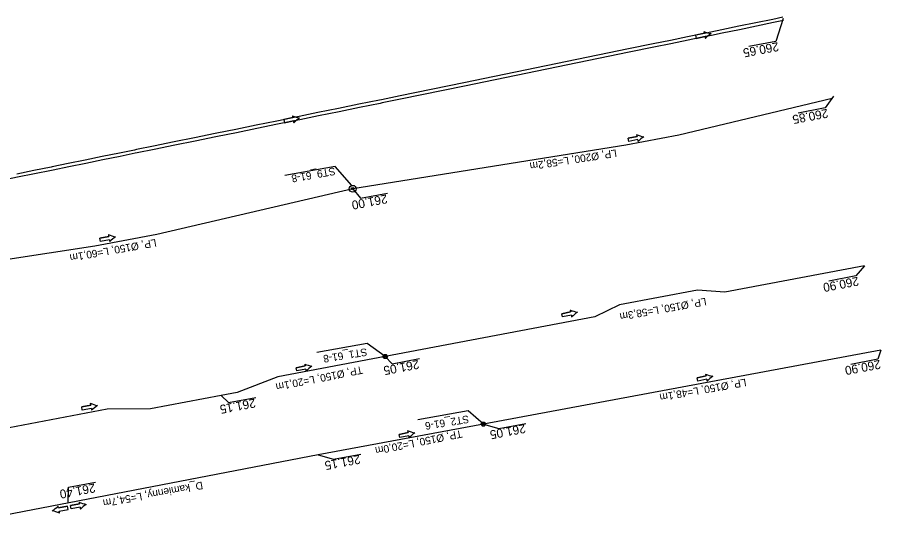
# Model space of a CAD drawing. Extents: x -1 to 65640748, y -22 to 5530284.
# Drawn here: x 6557517.6 to 6557620.4, y 5528681 to 5528743.4 of the extents above; entities that cross this region are included whole.
import ezdxf

# ---------------------------------------------------------------- set-up
doc = ezdxf.new("R2010")
doc.units = 0
for name, color, linetype in [('TOR_PROF-studnie i osadniki', 7, 'Continuous'), ('TOR_PS_ODW-drenaze', 7, 'Continuous'), ('TOR_PS_ODW-drenokolektory', 7, 'Continuous'), ('TOR_PS_ODW-studnie PEHD', 7, 'Continuous'), ('TOR_PS_OPIS_O-opisy rurociagow', 7, 'Continuous'), ('TOR_PS_OPIS_O-opisy studni', 7, 'Continuous'), ('TOR_PS_OPIS_T-INFO', 7, 'Continuous'), ('TOR_PS_T-rowy otwarte umocnione', 7, 'Continuous')]:
    doc.layers.add(name, color=color, linetype=linetype)

msp = doc.modelspace()

# ---------------------------------------------------------------- linework, layer by layer
at = {"layer": 'TOR_PROF-studnie i osadniki'}
for centre, radius in [((6557561.36, 5528703.01), 0.25), ((6557561.36, 5528703.01), 0.125), ((6557573.05, 5528694.97), 0.25), ((6557573.05, 5528694.97), 0.125)]:
    msp.add_circle(centre, radius, dxfattribs=at)
at = {"layer": 'TOR_PS_ODW-drenaze'}
for points in [[(6557620.36, 5528703.76), (6557573.05, 5528694.97)], [(6557561.36, 5528703.01), (6557548.59, 5528700.58), (6557543.74, 5528698.75), (6557541.85, 5528698.39)], [(6557541.85, 5528698.39), (6557533.42, 5528696.79), (6557528.24, 5528696.73), (6557502.37, 5528691.82)], [(6557573.05, 5528694.97), (6557553.38, 5528691.31)], [(6557553.38, 5528691.32), (6557499.62, 5528680.97)]]:
    msp.add_lwpolyline(points, dxfattribs=at)
at = {"layer": 'TOR_PS_ODW-drenokolektory'}
for points in [[(6557614.59, 5528733.72), (6557596.33, 5528729.36), (6557589.99, 5528728.16), (6557557.49, 5528722.98)], [(6557557.49, 5528722.98), (6557534.16, 5528717.55), (6557526.81, 5528716.13), (6557498.52, 5528711.81), (6557498.52, 5528711.81)], [(6557618.42, 5528713.82), (6557601.81, 5528710.67), (6557598.53, 5528710.92), (6557589.27, 5528709.16), (6557586.31, 5528707.74), (6557561.36, 5528703.01)]]:
    msp.add_lwpolyline(points, dxfattribs=at)
msp.add_circle((6557557.49, 5528722.98), 0.145, dxfattribs=at)
at = {"layer": 'TOR_PS_ODW-studnie PEHD'}
for centre, radius in [((6557557.49, 5528722.98), 0.4), ((6557561.36, 5528703.01), 0.25), ((6557561.36, 5528703.01), 0.112), ((6557573.05, 5528694.97), 0.25), ((6557573.05, 5528694.97), 0.112)]:
    msp.add_circle(centre, radius, dxfattribs=at)
at = {"layer": 'TOR_PS_OPIS_O-opisy rurociagow'}
for p, q in [((6557599.36, 5528741.48), (6557598.29, 5528741.26)), ((6557599.36, 5528741.48), (6557598.29, 5528741.26)), ((6557598.29, 5528741.26), (6557598.37, 5528740.87)), ((6557598.29, 5528741.26), (6557598.37, 5528740.87)), ((6557598.37, 5528740.87), (6557599.44, 5528741.09)), ((6557599.44, 5528741.09), (6557598.37, 5528740.87)), ((6557550.38, 5528731.44), (6557549.31, 5528731.23)), ((6557550.38, 5528731.44), (6557549.31, 5528731.23)), ((6557549.31, 5528731.23), (6557549.39, 5528730.83)), ((6557549.31, 5528731.23), (6557549.39, 5528730.83)), ((6557549.39, 5528730.83), (6557550.46, 5528731.05)), ((6557550.46, 5528731.05), (6557549.39, 5528730.83)), ((6557590.27, 5528728.99), (6557591.34, 5528729.21)), ((6557591.34, 5528729.21), (6557590.27, 5528728.99)), ((6557590.35, 5528728.6), (6557590.27, 5528728.99)), ((6557590.35, 5528728.6), (6557590.27, 5528728.99)), ((6557591.42, 5528728.82), (6557590.35, 5528728.6)), ((6557591.42, 5528728.82), (6557590.35, 5528728.6)), ((6557527.39, 5528717.08), (6557528.46, 5528717.3)), ((6557528.46, 5528717.3), (6557527.39, 5528717.08)), ((6557527.47, 5528716.69), (6557527.39, 5528717.08)), ((6557527.47, 5528716.69), (6557527.39, 5528717.08)), ((6557528.54, 5528716.91), (6557527.47, 5528716.69)), ((6557528.54, 5528716.91), (6557527.47, 5528716.69)), ((6557582.37, 5528708.11), (6557583.44, 5528708.33)), ((6557583.44, 5528708.33), (6557582.37, 5528708.11)), ((6557582.46, 5528707.72), (6557582.37, 5528708.11)), ((6557582.46, 5528707.72), (6557582.37, 5528708.11)), ((6557583.53, 5528707.94), (6557582.46, 5528707.72)), ((6557583.53, 5528707.94), (6557582.46, 5528707.72)), ((6557550.77, 5528701.68), (6557551.84, 5528701.9)), ((6557551.84, 5528701.9), (6557550.77, 5528701.68)), ((6557550.85, 5528701.29), (6557550.77, 5528701.68)), ((6557550.85, 5528701.29), (6557550.77, 5528701.68)), ((6557551.92, 5528701.51), (6557550.85, 5528701.29)), ((6557551.92, 5528701.51), (6557550.85, 5528701.29)), ((6557598.5, 5528700.48), (6557599.57, 5528700.7)), ((6557599.57, 5528700.7), (6557598.5, 5528700.48)), ((6557598.58, 5528700.09), (6557598.5, 5528700.48)), ((6557598.58, 5528700.09), (6557598.5, 5528700.48)), ((6557599.65, 5528700.31), (6557598.58, 5528700.09)), ((6557599.65, 5528700.31), (6557598.58, 5528700.09)), ((6557525.23, 5528697.04), (6557526.3, 5528697.23)), ((6557526.3, 5528697.23), (6557525.23, 5528697.04)), ((6557525.3, 5528696.64), (6557525.23, 5528697.04)), ((6557525.3, 5528696.64), (6557525.23, 5528697.04)), ((6557526.38, 5528696.84), (6557525.3, 5528696.64)), ((6557526.38, 5528696.84), (6557525.3, 5528696.64)), ((6557563.01, 5528693.75), (6557564.08, 5528693.97)), ((6557564.08, 5528693.97), (6557563.01, 5528693.75)), ((6557563.09, 5528693.36), (6557563.01, 5528693.75)), ((6557563.09, 5528693.36), (6557563.01, 5528693.75)), ((6557564.16, 5528693.58), (6557563.09, 5528693.36)), ((6557564.16, 5528693.58), (6557563.09, 5528693.36)), ((6557523.52, 5528685.21), (6557522.45, 5528685)), ((6557522.45, 5528685), (6557523.52, 5528685.21)), ((6557523.6, 5528684.82), (6557523.52, 5528685.21)), ((6557523.6, 5528684.82), (6557523.52, 5528685.21)), ((6557523.89, 5528685.28), (6557524.96, 5528685.47)), ((6557524.96, 5528685.47), (6557523.89, 5528685.28)), ((6557523.96, 5528684.89), (6557523.89, 5528685.28)), ((6557523.96, 5528684.89), (6557523.89, 5528685.28)), ((6557525.03, 5528685.08), (6557523.96, 5528684.89)), ((6557525.03, 5528685.08), (6557523.96, 5528684.89)), ((6557522.53, 5528684.61), (6557523.6, 5528684.82)), ((6557522.53, 5528684.61), (6557523.6, 5528684.82))]:
    msp.add_line(p, q, dxfattribs=at)
for points in [[(6557599.3, 5528741.7), (6557599.3, 5528741.7)], [(6557599.47, 5528740.87), (6557599.47, 5528740.87)], [(6557550.32, 5528731.66), (6557550.32, 5528731.66)], [(6557550.49, 5528730.83), (6557550.49, 5528730.83)], [(6557591.29, 5528729.43), (6557591.29, 5528729.43)], [(6557591.46, 5528728.59), (6557591.46, 5528728.59)], [(6557528.41, 5528717.52), (6557528.41, 5528717.52)], [(6557528.58, 5528716.69), (6557528.58, 5528716.69)], [(6557583.39, 5528708.55), (6557583.39, 5528708.55)], [(6557583.56, 5528707.71), (6557583.56, 5528707.71)], [(6557551.78, 5528702.12), (6557551.78, 5528702.12)], [(6557551.96, 5528701.29), (6557551.96, 5528701.29)], [(6557599.51, 5528700.92), (6557599.51, 5528700.92)], [(6557599.68, 5528700.08), (6557599.68, 5528700.08)], [(6557526.25, 5528697.45), (6557526.25, 5528697.45)], [(6557526.4, 5528696.61), (6557526.4, 5528696.61)], [(6557564.03, 5528694.19), (6557564.03, 5528694.19)], [(6557564.2, 5528693.36), (6557564.2, 5528693.36)], [(6557522.41, 5528685.22), (6557522.41, 5528685.22)], [(6557524.91, 5528685.69), (6557524.91, 5528685.69)], [(6557522.58, 5528684.39), (6557522.58, 5528684.39)], [(6557525.06, 5528684.86), (6557525.06, 5528684.86)]]:
    msp.add_lwpolyline(points, dxfattribs=at)
for centre, radius, start, end in [((6557601.15, 5528746.26), 4.92, 247.9079, 258.2898), ((6557599.76, 5528741.7), 0.458, 180.0225, 208.4837), ((6557601.15, 5528746.26), 4.92, 247.9079, 258.2898), ((6557599.76, 5528741.7), 0.458, 180.0225, 208.4837), ((6557602.97, 5528737.41), 4.92, 124.9458, 135.3277), ((6557602.97, 5528737.41), 4.92, 124.9458, 135.3277), ((6557599.9, 5528741.05), 0.458, 174.7519, 203.2131), ((6557599.9, 5528741.05), 0.458, 174.7519, 203.2131), ((6557552.18, 5528736.22), 4.92, 247.8203, 258.2021), ((6557550.78, 5528731.66), 0.458, 179.9349, 208.3961), ((6557552.18, 5528736.22), 4.92, 247.8203, 258.2021), ((6557550.78, 5528731.66), 0.458, 179.9349, 208.3961), ((6557553.98, 5528727.37), 4.92, 124.8582, 135.24), ((6557553.98, 5528727.37), 4.92, 124.8582, 135.24), ((6557550.91, 5528731.01), 0.458, 174.6642, 203.1255), ((6557550.91, 5528731.01), 0.458, 174.6642, 203.1255), ((6557591.75, 5528729.43), 0.458, 180.0627, 208.524), ((6557593.13, 5528733.98), 4.92, 247.9482, 258.33), ((6557593.13, 5528733.98), 4.92, 247.9482, 258.33), ((6557591.75, 5528729.43), 0.458, 180.0627, 208.524), ((6557594.96, 5528725.14), 4.92, 124.9861, 135.3679), ((6557594.96, 5528725.14), 4.92, 124.9861, 135.3679), ((6557591.88, 5528728.77), 0.458, 174.7921, 203.2533), ((6557591.88, 5528728.77), 0.458, 174.7921, 203.2533), ((6557528.87, 5528717.52), 0.458, 180.0627, 208.524), ((6557530.25, 5528722.08), 4.92, 247.9482, 258.33), ((6557530.25, 5528722.08), 4.92, 247.9482, 258.33), ((6557528.87, 5528717.52), 0.458, 180.0627, 208.524), ((6557529, 5528716.87), 0.458, 174.7921, 203.2533), ((6557529, 5528716.87), 0.458, 174.7921, 203.2533), ((6557532.08, 5528713.23), 4.92, 124.9861, 135.3679), ((6557532.08, 5528713.23), 4.92, 124.9861, 135.3679), ((6557583.85, 5528708.55), 0.458, 180.0627, 208.524), ((6557585.24, 5528713.1), 4.92, 247.9482, 258.33), ((6557585.24, 5528713.1), 4.92, 247.9482, 258.33), ((6557583.85, 5528708.55), 0.458, 180.0627, 208.524), ((6557583.98, 5528707.89), 0.458, 174.7921, 203.2533), ((6557583.98, 5528707.89), 0.458, 174.7921, 203.2533), ((6557587.06, 5528704.26), 4.92, 124.9861, 135.3679), ((6557587.06, 5528704.26), 4.92, 124.9861, 135.3679), ((6557552.24, 5528702.12), 0.458, 180.0627, 208.524), ((6557553.63, 5528706.68), 4.92, 247.9482, 258.33), ((6557553.63, 5528706.68), 4.92, 247.9482, 258.33), ((6557552.24, 5528702.12), 0.458, 180.0627, 208.524), ((6557552.38, 5528701.47), 0.458, 174.7921, 203.2533), ((6557552.38, 5528701.47), 0.458, 174.7921, 203.2533), ((6557555.46, 5528697.83), 4.92, 124.9861, 135.3679), ((6557555.46, 5528697.83), 4.92, 124.9861, 135.3679), ((6557599.97, 5528700.92), 0.458, 180.0627, 208.524), ((6557601.36, 5528705.47), 4.92, 247.9482, 258.33), ((6557601.36, 5528705.47), 4.92, 247.9482, 258.33), ((6557599.97, 5528700.92), 0.458, 180.0627, 208.524), ((6557600.11, 5528700.26), 0.458, 174.7921, 203.2533), ((6557600.11, 5528700.26), 0.458, 174.7921, 203.2533), ((6557603.18, 5528696.63), 4.92, 124.9861, 135.3679), ((6557603.18, 5528696.63), 4.92, 124.9861, 135.3679), ((6557526.71, 5528697.44), 0.458, 178.6495, 207.1107), ((6557528.21, 5528701.96), 4.92, 246.5349, 256.9167), ((6557528.21, 5528701.96), 4.92, 246.5349, 256.9167), ((6557526.71, 5528697.44), 0.458, 178.6495, 207.1107), ((6557526.83, 5528696.78), 0.458, 173.3788, 201.8401), ((6557526.83, 5528696.78), 0.458, 173.3788, 201.8401), ((6557529.82, 5528693.07), 4.92, 123.5728, 133.9546), ((6557529.82, 5528693.07), 4.92, 123.5728, 133.9546), ((6557564.49, 5528694.19), 0.458, 180.0627, 208.524), ((6557565.87, 5528698.75), 4.92, 247.9482, 258.33), ((6557565.87, 5528698.75), 4.92, 247.9482, 258.33), ((6557564.49, 5528694.19), 0.458, 180.0627, 208.524), ((6557564.62, 5528693.54), 0.458, 174.7921, 203.2533), ((6557564.62, 5528693.54), 0.458, 174.7921, 203.2533), ((6557567.7, 5528689.9), 4.92, 124.9861, 135.3679), ((6557567.7, 5528689.9), 4.92, 124.9861, 135.3679), ((6557518.94, 5528688.7), 4.92, 304.5497, 314.9316), ((6557518.94, 5528688.7), 4.92, 304.5497, 314.9316), ((6557521.99, 5528685.04), 0.458, 354.3558, 22.817), ((6557521.99, 5528685.04), 0.458, 354.3558, 22.817), ((6557525.37, 5528685.68), 0.458, 178.6495, 207.1107), ((6557526.87, 5528690.21), 4.92, 246.5349, 256.9167), ((6557526.87, 5528690.21), 4.92, 246.5349, 256.9167), ((6557525.37, 5528685.68), 0.458, 178.6495, 207.1107), ((6557525.49, 5528685.03), 0.458, 173.3788, 201.8401), ((6557525.49, 5528685.03), 0.458, 173.3788, 201.8401), ((6557528.48, 5528681.32), 4.92, 123.5728, 133.9546), ((6557528.48, 5528681.32), 4.92, 123.5728, 133.9546), ((6557520.7, 5528679.84), 4.92, 67.5119, 77.8937), ((6557520.7, 5528679.84), 4.92, 67.5119, 77.8937), ((6557522.12, 5528684.39), 0.458, 359.6264, 28.0877), ((6557522.12, 5528684.39), 0.458, 359.6264, 28.0877)]:
    msp.add_arc(centre, radius, start, end, dxfattribs=at)
at = {"layer": 'TOR_PS_OPIS_T-INFO'}
for points in [[(6557608.76, 5528743.22), (6557607.87, 5528740.52), (6557604.64, 5528739.89)], [(6557614.73, 5528734.01), (6557613.76, 5528732.59), (6557610.53, 5528731.96)], [(6557557.39, 5528723.35), (6557555.39, 5528725.63), (6557549.42, 5528724.57)], [(6557557.49, 5528722.98), (6557558.41, 5528721.85), (6557561.65, 5528722.45)], [(6557618.42, 5528713.82), (6557617.41, 5528712.6), (6557614.18, 5528711.98)], [(6557561.36, 5528703.01), (6557559.2, 5528704.57), (6557553.23, 5528703.51)], [(6557620.36, 5528703.76), (6557620.01, 5528702.7), (6557616.78, 5528702.08)], [(6557561.34, 5528703), (6557562.19, 5528702.16), (6557565.43, 5528702.76)], [(6557541.85, 5528698.39), (6557542.71, 5528697.55), (6557545.95, 5528698.15)], [(6557573.05, 5528694.97), (6557571.22, 5528696.53), (6557565.24, 5528695.47)], [(6557573.05, 5528694.97), (6557574.87, 5528694.44), (6557578.11, 5528695.05)], [(6557553.38, 5528691.31), (6557555.21, 5528690.79), (6557558.44, 5528691.39)], [(6557523.61, 5528685.66), (6557523.64, 5528687.45), (6557526.88, 5528688.05)]]:
    msp.add_lwpolyline(points, dxfattribs=at)
at = {"layer": 'TOR_PS_T-rowy otwarte umocnione'}
for points in [[(6557608.78, 5528742.99), (6557607.6, 5528742.75), (6557605.56, 5528742.33), (6557603.53, 5528741.91), (6557601.49, 5528741.5), (6557600.19, 5528741.23), (6557599.46, 5528741.08), (6557597.42, 5528740.66), (6557595.38, 5528740.24), (6557593.35, 5528739.82), (6557590.4, 5528739.22), (6557580.6, 5528737.2), (6557570.8, 5528735.19), (6557570.8, 5528735.19), (6557570.8, 5528735.19), (6557563.2, 5528733.64), (6557561, 5528733.19), (6557560.76, 5528733.14), (6557558.31, 5528732.64), (6557555.87, 5528732.14), (6557553.42, 5528731.65), (6557551.2, 5528731.19), (6557550.97, 5528731.15), (6557548.53, 5528730.65), (6557546.08, 5528730.15), (6557543.64, 5528729.65), (6557541.41, 5528729.19), (6557541.19, 5528729.15), (6557538.75, 5528728.65), (6557536.3, 5528728.15), (6557533.86, 5528727.66), (6557531.82, 5528727.24), (6557531.61, 5528727.2), (6557529.79, 5528726.83), (6557527.75, 5528726.41), (6557525.72, 5528726), (6557523.69, 5528725.58), (6557521.81, 5528725.2), (6557521.65, 5528725.17), (6557519.62, 5528724.75), (6557517.58, 5528724.34), (6557515.55, 5528723.92)], [(6557608.7, 5528743.39), (6557607.53, 5528743.14), (6557605.49, 5528742.73), (6557603.45, 5528742.31), (6557601.42, 5528741.89), (6557600.12, 5528741.62), (6557599.38, 5528741.47), (6557597.35, 5528741.05), (6557595.31, 5528740.63), (6557593.27, 5528740.22), (6557590.32, 5528739.61), (6557580.53, 5528737.6), (6557570.73, 5528735.58), (6557570.73, 5528735.58), (6557570.73, 5528735.58), (6557563.13, 5528734.03), (6557560.93, 5528733.58), (6557560.68, 5528733.53), (6557558.24, 5528733.04), (6557555.79, 5528732.54), (6557553.35, 5528732.04), (6557551.13, 5528731.59), (6557550.9, 5528731.54), (6557548.45, 5528731.04), (6557546.01, 5528730.54), (6557543.56, 5528730.04), (6557541.33, 5528729.59), (6557541.12, 5528729.54), (6557538.67, 5528729.05), (6557536.23, 5528728.55), (6557533.78, 5528728.05), (6557531.75, 5528727.63), (6557531.53, 5528727.59), (6557529.71, 5528727.22), (6557527.68, 5528726.8), (6557525.65, 5528726.39), (6557523.61, 5528725.97), (6557521.73, 5528725.59), (6557521.58, 5528725.56), (6557519.54, 5528725.14), (6557517.51, 5528724.73)]]:
    msp.add_lwpolyline(points, dxfattribs=at)

# ---------------------------------------------------------------- texts
at = {"layer": 'TOR_PS_OPIS_O-opisy rurociagow'}
for s, rotation, p in [('LP, Ø200, L=58,2m', 188.7306, (6557588.86, 5528727.67)), ('LP, Ø150, L=60,1m', 190.0927, (6557534.04, 5528717.01)), ('LP, Ø150, L=58,3m', 190.0927, (6557599.52, 5528710.01)), ('TP, Ø150, L=20,1m', 191.303, (6557558.59, 5528701.87)), ('LP, Ø150, L=48,1m', 190.0927, (6557604.27, 5528700.39)), ('TP, Ø150, L=20,0m', 191.303, (6557570.43, 5528694.27)), ('D_kamienny, L=54,7m', 190.3457, (6557539.57, 5528688.14))]:
    msp.add_text(s, height=0.9, rotation=rotation, dxfattribs=at).set_placement(p)
at = {"layer": 'TOR_PS_OPIS_O-opisy studni'}
for s, rotation, p in [('ST9_61-8', 190.1463, (6557555.34, 5528725.53)), ('ST1_61-8', 189.3186, (6557559.14, 5528704.01)), ('ST2_61-6', 189.2717, (6557571.26, 5528696.02))]:
    msp.add_text(s, height=0.9, rotation=rotation, dxfattribs=at).set_placement(p)
at = {"layer": 'TOR_PS_OPIS_T-INFO'}
for s, rotation, p in [('260.65', 190.7159, (6557608.11, 5528740.43)), ('260.85', 190.7159, (6557613.99, 5528732.5)), ('261.00', 190.7506, (6557561.52, 5528722.31)), ('260.90', 190.7159, (6557617.64, 5528712.51)), ('261.05', 190.7506, (6557565.3, 5528702.62)), ('260.90', 190.7159, (6557620.24, 5528702.62)), ('261.15', 190.7506, (6557545.82, 5528698.01)), ('261.05', 190.7506, (6557577.97, 5528694.98)), ('261.15', 190.7506, (6557558.3, 5528691.32)), ('261.40', 190.7506, (6557526.75, 5528687.91))]:
    msp.add_text(s, height=1.05, rotation=rotation, dxfattribs=at).set_placement(p)

doc.saveas('drawing.dxf')
